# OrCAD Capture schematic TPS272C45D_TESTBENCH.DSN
size D
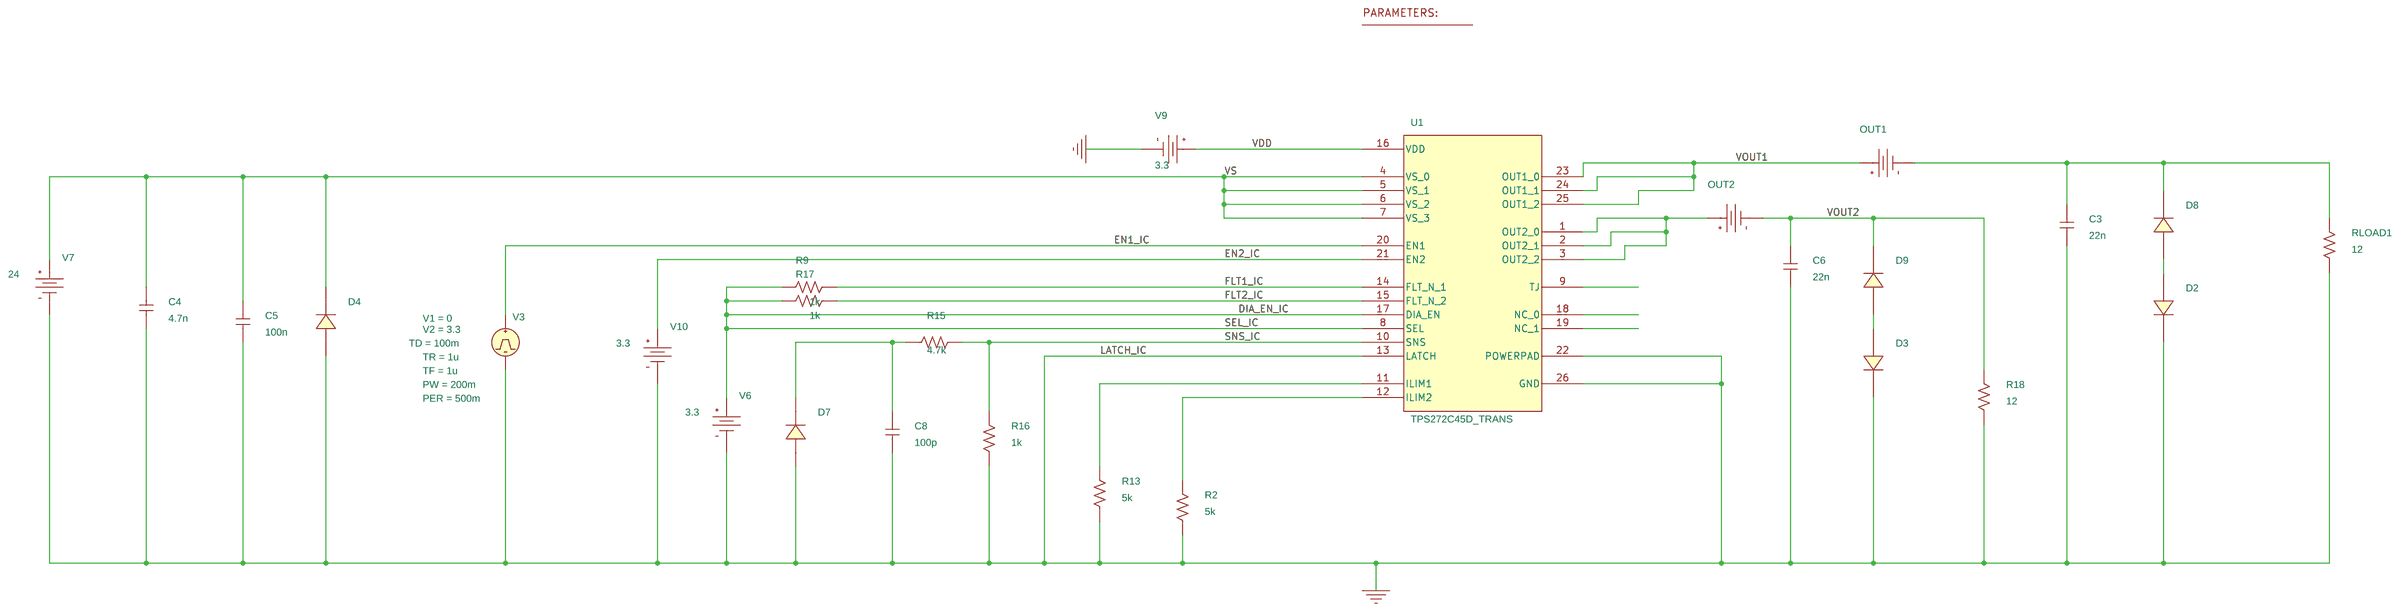
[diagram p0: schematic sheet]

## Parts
1  PARAM
C3  22n  [RAD/CK05]
C4  4.7n  [RAD/CK05]
C5  100n  [RAD/CK05]
C6  22n  [RAD/CK05]
C8  100p  [RAD/CK05]
D2  SMAJ48A
D3  SMAJ48A
D4  SMBJ33A
D7  MMSZ5226B
D8  STPS1150A  [SMA]
D9  STPS1150A  [SMA]
OUT1  VDC
OUT2  VDC
R2  5k  [AX/RC05]
R9  1k  [AX/RC05]
R13  5k  [AX/RC05]
R15  4.7k  [AX/RC05]
R16  1k  [AX/RC05]
R17  1k  [AX/RC05]
R18  12  [AX/RC05]
RLOAD1  12  [AX/RC05]
U1  TPS272C45D_TRANS
V3  VPULSE
V6  VDC
V7  VDC
V9  VDC
V10  VDC

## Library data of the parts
1 = PARAM: Temp_Amb: 45
C3-C6 C8 = C
D2-D4 = DD
D7 = DD: PSpiceTemplate: X^@REFDES  %A %C @MODEL
D8 D9 = STPS1150A
OUT1 OUT2 = VDC
R2 R9 R13 R15-R18 RLOAD1 = R
U1 = TPS272C45D_TRANS
V3 = VPULSE: PER: 500m; PW: 200m; TD: 100m; TF: 1u; TR: 1u; V1: 0; V2: 3.3
V6 V9 V10 = VDC: DC: 3.3
V7 = VDC: DC: 24

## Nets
VDD: U1.16(VDD) V9.0(+)
0: C3.1 C4.1 C5.1 C6.1 C8.1 D2.1(C) D3.1(C) D4.2(A) D7.2(A) R2.1 R13.1 R16.1 R18.1 RLOAD1.1 U1.13(LATCH) U1.22(POWERPAD) U1.26(GND) V3.2(-) V6.1(-) V7.1(-) V9.1(-) V10.1(-)
DIA_EN_IC: R9.2 R17.2 U1.8(SEL) U1.17(DIA_EN) V6.0(+)
EN1_IC: U1.20(EN1) V3.1(+)
EN2_IC: U1.21(EN2) V10.0(+)
FLT1_IC: R9.1 U1.14(FLT_N_1)
FLT2_IC: R17.1 U1.15(FLT_N_2)
SNS_IC: R15.2 R16.2 U1.10(SNS)
VOUT1: OUT1.0(+) U1.23(OUT1_0) U1.24(OUT1_1) U1.25(OUT1_2)
VOUT2: C6.2 D9.1(C) OUT2.1(-) R18.2
VS: C4.2 C5.2 D4.1(C) U1.4(VS_0) U1.5(VS_1) U1.6(VS_2) U1.7(VS_3) V7.0(+)
N65481: C3.2 D8.1(C) OUT1.1(-) RLOAD1.2
N65619: OUT2.0(+) U1.1(OUT2_0) U1.2(OUT2_1) U1.3(OUT2_2)
N65797: D2.2(A) D8.2(A)
N65979: D3.2(A) D9.2(A)
N66181: C8.2 D7.1(C) R15.1
N66301: R13.2 U1.11(ILIM1)
N66349: R2.2 U1.12(ILIM2)

Not connected (* = marked no-connect by the designer): U1 9(TJ) 18(NC_0) 19(NC_1)
